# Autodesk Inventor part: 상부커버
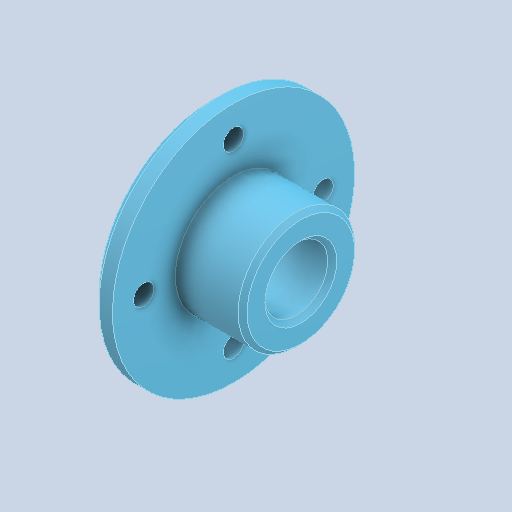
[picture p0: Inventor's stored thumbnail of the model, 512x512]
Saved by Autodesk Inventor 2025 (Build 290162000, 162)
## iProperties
Created: 2024-07
Part Number: 상부커버
Material: 알루미늄 6061
Document SubType Name: Modeling
Designer: deana
Density: 2.71 g/cm^3
Appearance: 기본값
Author: jhkim
Sending System: Autodesk Inventor 2025
Preprocessor: ST-DEVELOPER v20
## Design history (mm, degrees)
feature "솔리드1"
node "솔리드2"
